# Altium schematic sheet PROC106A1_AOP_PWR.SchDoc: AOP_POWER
size 431 x 279 mm; Date: Not shown in title block; ApprovedBy: Not shown in title block; CheckedBy: Not shown in title block; Author: Not shown in title block; CompanyName: Not shown in title block; DrawnBy: Antony/Anand Ram; Engineer: Not shown in title block; Organization: Not shown in title block; Address1: Not shown in title block; Address2: Not shown in title block; Address3: Not shown in title block; Address4: Not shown in title block; DocumentNumber: 4; Revision: Use project parameter SCH_Rev; SheetNumber: 4; SheetTotal: 12; PageSetup: Record=PageOptions¦CenterHorizontal=True¦CenterVertical=True¦PrintScale=1.00¦XCorrection=1.00¦YCorrection=1.00¦PrintKind=0¦BorderSize=5000000¦LeftOffset=0¦BottomOffset=0¦Orientation=2¦PaperLength=1000¦PaperWidth=1000¦Scale=100¦PaperSource=15¦PrintQuality=600¦MediaType=1¦DitherType=10¦PaperKind=Letter¦PrintScaleMode=1
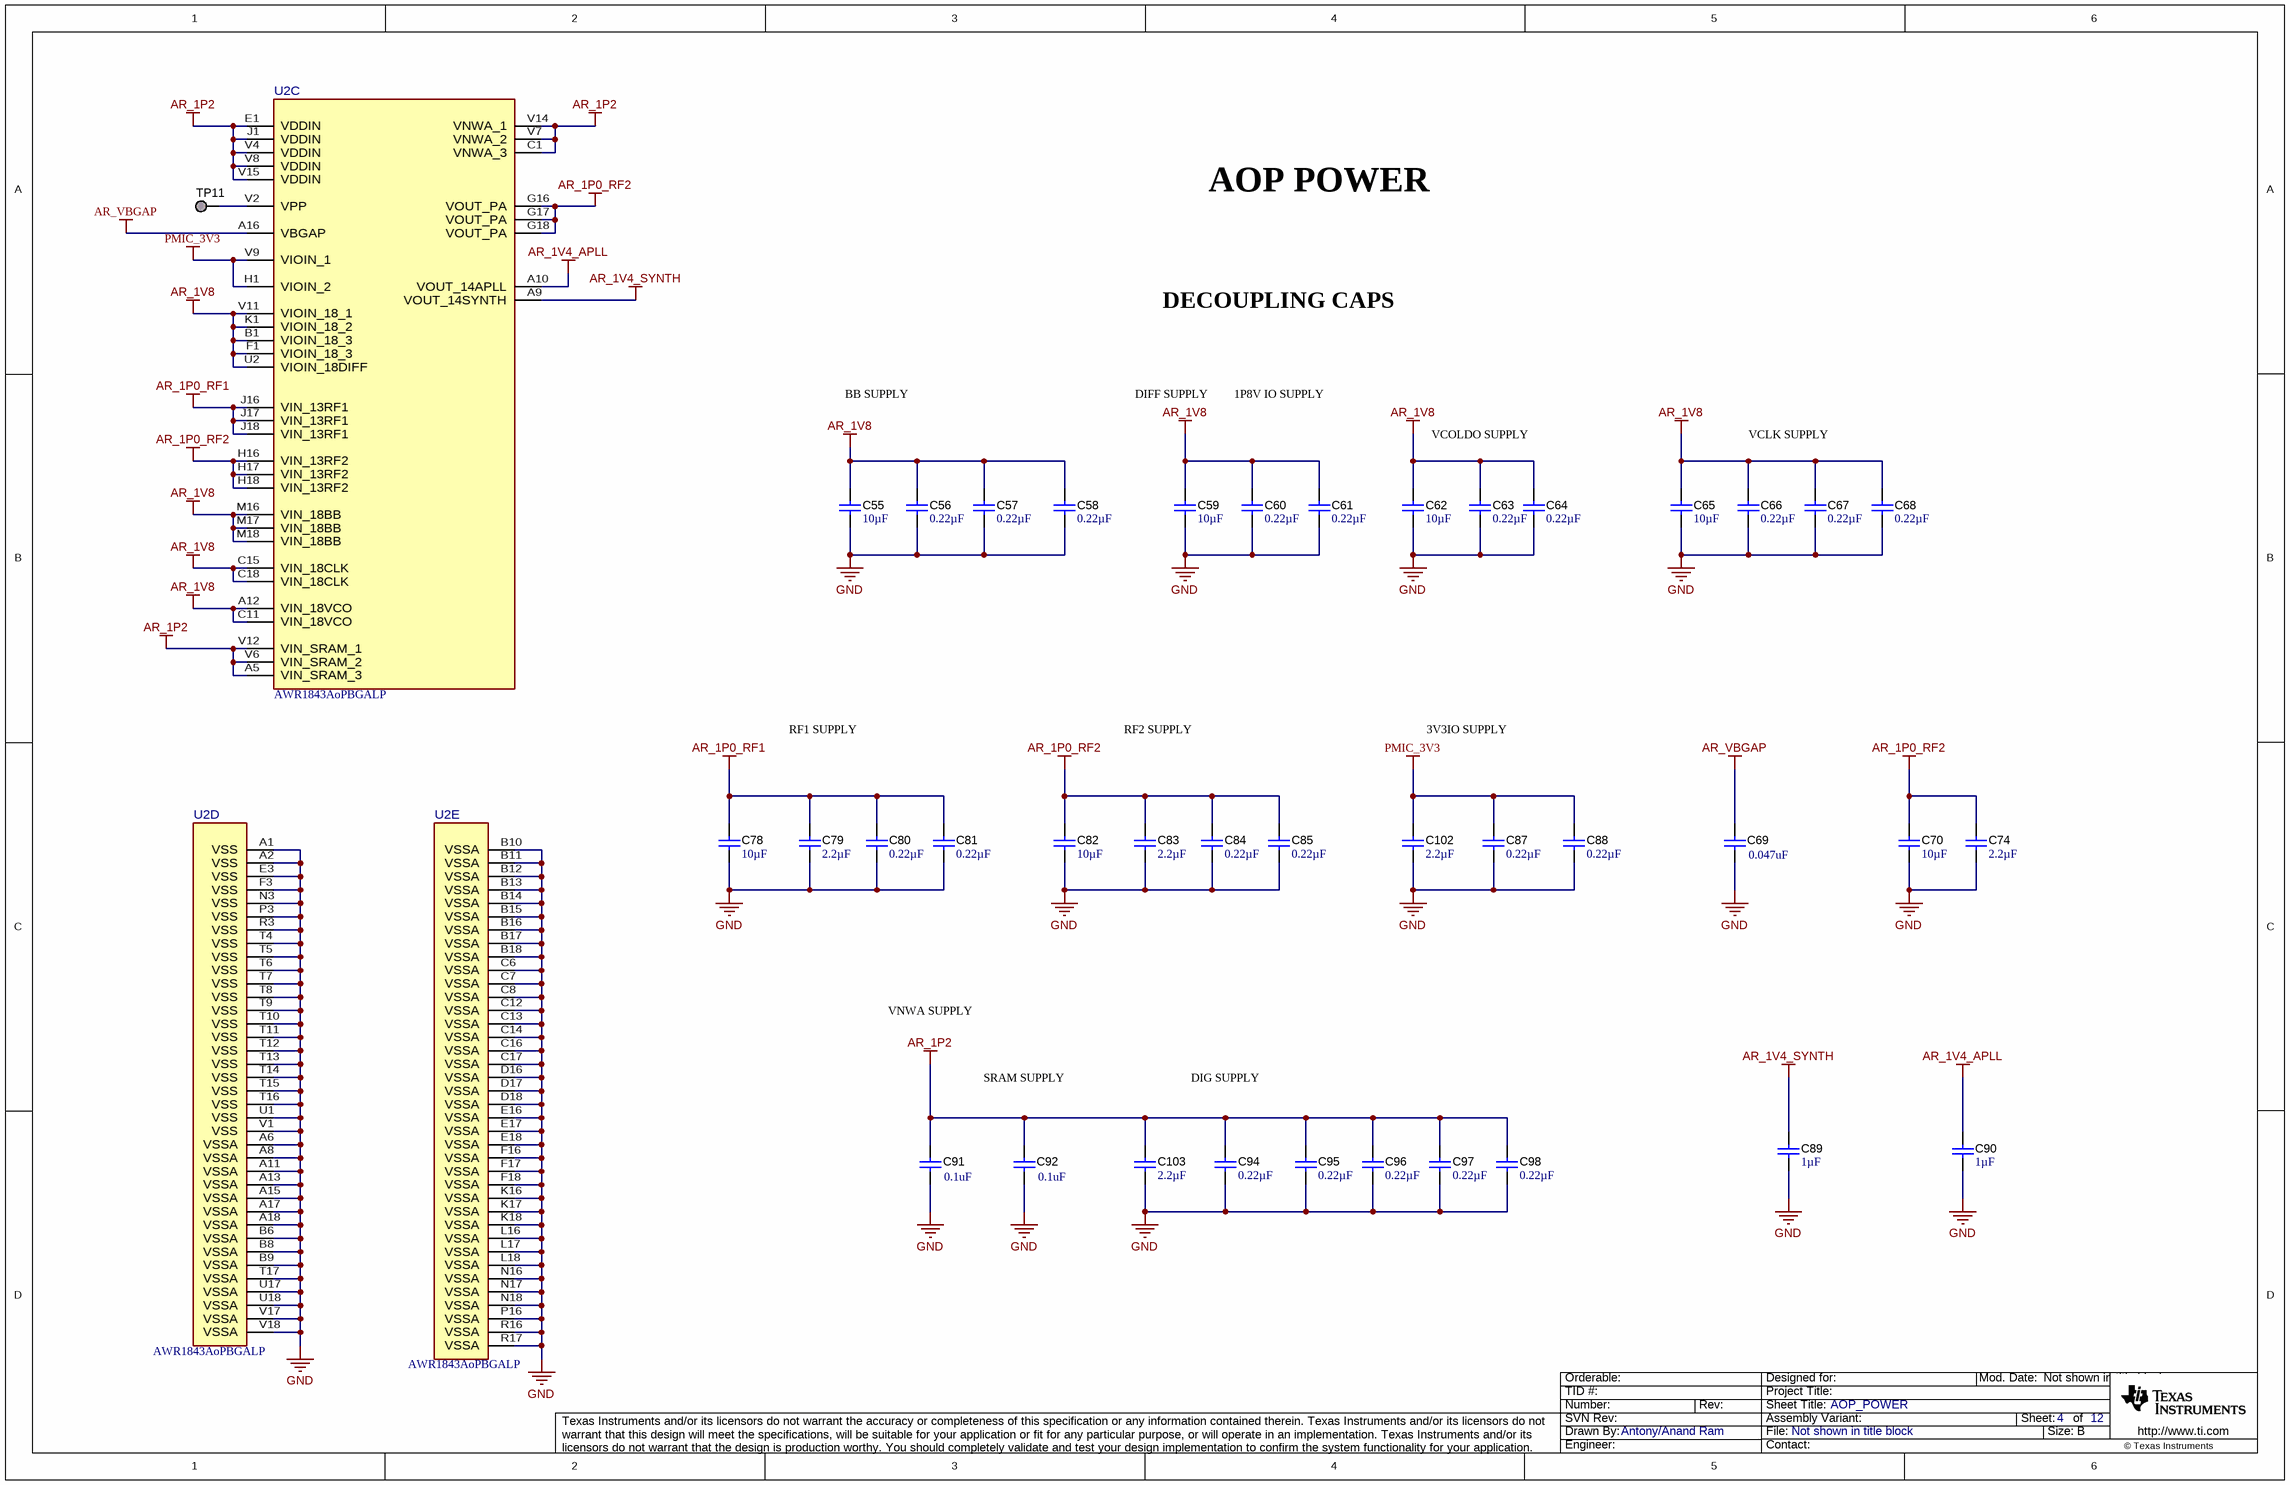
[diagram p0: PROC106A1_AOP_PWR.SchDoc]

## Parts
C55  Cap_F: 10µF  [0805L]  (hidden comment: GCM21BR71A106KE22L)
C56  ValueDisplayed: 0.22µF  [0402L]  (hidden comment: GCM155R71C224KE02D)
C57  ValueDisplayed: 0.22µF  [0402L]  (hidden comment: GCM155R71C224KE02D)
C58  ValueDisplayed: 0.22µF  [0402L]  (hidden comment: GCM155R71C224KE02D)
C59  Cap_F: 10µF  [0805L]  (hidden comment: GCM21BR71A106KE22L)
C60  ValueDisplayed: 0.22µF  [0402L]  (hidden comment: GCM155R71C224KE02D)
C61  ValueDisplayed: 0.22µF  [0402L]  (hidden comment: GCM155R71C224KE02D)
C62  Cap_F: 10µF  [0805L]  (hidden comment: GCM21BR71A106KE22L)
C63  ValueDisplayed: 0.22µF  [0402L]  (hidden comment: GCM155R71C224KE02D)
C64  ValueDisplayed: 0.22µF  [0402L]  (hidden comment: GCM155R71C224KE02D)
C65  Cap_F: 10µF  [0805L]  (hidden comment: GCM21BR71A106KE22L)
C66  ValueDisplayed: 0.22µF  [0402L]  (hidden comment: GCM155R71C224KE02D)
C67  ValueDisplayed: 0.22µF  [0402L]  (hidden comment: GCM155R71C224KE02D)
C68  ValueDisplayed: 0.22µF  [0402L]  (hidden comment: GCM155R71C224KE02D)
C69  ValueDisplayed: 0.047uF  [0402L]  (hidden comment: CGA2B3X7R1H473K050BB)
C70  Cap_F: 10µF  [0805L]  (hidden comment: GCM21BR71A106KE22L)
C74  Cap_F: 2.2µF  [0603L]  (hidden comment: GCM188R70J225KE22D)
C78  Cap_F: 10µF  [0805L]  (hidden comment: GCM21BR71A106KE22L)
C79  Cap_F: 2.2µF  [0603L]  (hidden comment: GCM188R70J225KE22D)
C80  ValueDisplayed: 0.22µF  [0402L]  (hidden comment: GCM155R71C224KE02D)
C81  ValueDisplayed: 0.22µF  [0402L]  (hidden comment: GCM155R71C224KE02D)
C82  Cap_F: 10µF  [0805L]  (hidden comment: GCM21BR71A106KE22L)
C83  Cap_F: 2.2µF  [0603L]  (hidden comment: GCM188R70J225KE22D)
C84  ValueDisplayed: 0.22µF  [0402L]  (hidden comment: GCM155R71C224KE02D)
C85  ValueDisplayed: 0.22µF  [0402L]  (hidden comment: GCM155R71C224KE02D)
C87  ValueDisplayed: 0.22µF  [0402L]  (hidden comment: GCM155R71C224KE02D)
C88  ValueDisplayed: 0.22µF  [0402L]  (hidden comment: GCM155R71C224KE02D)
C89  Cap_F: 1µF  [0603L]  (hidden comment: GCM188R71C105KA64D)
C90  Cap_F: 1µF  [0603L]  (hidden comment: GCM188R71C105KA64D)
C91  ValueDisplayed: 0.1uF  [0402L]  (hidden comment: GCM155R71C104KA55D)
C92  ValueDisplayed: 0.1uF  [0402L]  (hidden comment: GCM155R71C104KA55D)
C94  ValueDisplayed: 0.22µF  [0402L]  (hidden comment: GCM155R71C224KE02D)
C95  ValueDisplayed: 0.22µF  [0402L]  (hidden comment: GCM155R71C224KE02D)
C96  ValueDisplayed: 0.22µF  [0402L]  (hidden comment: GCM155R71C224KE02D)
C97  ValueDisplayed: 0.22µF  [0402L]  (hidden comment: GCM155R71C224KE02D)
C98  ValueDisplayed: 0.22µF  [0402L]  (hidden comment: GCM155R71C224KE02D)
C102  Cap_F: 2.2µF  [0603L]  (hidden comment: GCM188R70J225KE22D)
C103  Cap_F: 2.2µF  [0603L]  (hidden comment: GCM188R70J225KE22D)
TP11  TP_SM_1MM  [TP_SM_1MM]  (value not drawn)  (no BOM)
U2  AWR1843AoPBGALP  [ALP0180A-MFG]  (parts C,D,E of 5)

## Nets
AR_1P0_RF1: C78.1 C79.1 C80.1 C81.1 U2.J16(VIN_13RF1) U2.J17(VIN_13RF1) U2.J18(VIN_13RF1)
AR_1P0_RF2: C70.1 C74.1 C82.1 C83.1 C84.1 C85.1 U2.G16(VOUT_PA) U2.G17(VOUT_PA) U2.G18(VOUT_PA) U2.H16(VIN_13RF2) U2.H17(VIN_13RF2) U2.H18(VIN_13RF2)
AR_1P2: C91.2 C92.2 C94.1 C95.1 C96.1 C97.1 C98.1 C103.1 U2.A5(VIN_SRAM_3) U2.C1(VNWA_3) U2.E1(VDDIN) U2.J1(VDDIN) U2.V4(VDDIN) U2.V6(VIN_SRAM_2) U2.V7(VNWA_2) U2.V8(VDDIN) U2.V12(VIN_SRAM_1) U2.V14(VNWA_1) U2.V15(VDDIN)
AR_1V4_APLL: C90.1 U2.A10(VOUT_14APLL)
AR_1V4_SYNTH: C89.1 U2.A9(VOUT_14SYNTH)
AR_1V8: C55.1 C56.1 C57.1 C58.1 C59.1 C60.1 C61.1 C62.1 C63.1 C64.1 C65.1 C66.1 C67.1 C68.1 U2.A12(VIN_18VCO) U2.B1(VIOIN_18_3) U2.C11(VIN_18VCO) U2.C15(VIN_18CLK) U2.C18(VIN_18CLK) U2.F1(VIOIN_18_3) U2.K1(VIOIN_18_2) U2.M16(VIN_18BB) U2.M17(VIN_18BB) U2.M18(VIN_18BB) U2.U2(VIOIN_18DIFF) U2.V11(VIOIN_18_1)
AR_VBGAP: C69.1 U2.A16(VBGAP)
GND: C55.2 C56.2 C57.2 C58.2 C59.2 C60.2 C61.2 C62.2 C63.2 C64.2 C65.2 C66.2 C67.2 C68.2 C69.2 C70.2 C74.2 C78.2 C79.2 C80.2 C81.2 C82.2 C83.2 C84.2 C85.2 C87.2 C88.2 C89.2 C90.2 C91.1 C92.1 C94.2 C95.2 C96.2 C97.2 C98.2 C102.2 C103.2 U2.A1(VSS) U2.A2(VSS) U2.A6(VSSA) U2.A8(VSSA) U2.A11(VSSA) U2.A13(VSSA) U2.A15(VSSA) U2.A17(VSSA) U2.A18(VSSA) U2.B6(VSSA) U2.B8(VSSA) U2.B9(VSSA) U2.B10(VSSA) U2.B11(VSSA) U2.B12(VSSA) U2.B13(VSSA) U2.B14(VSSA) U2.B15(VSSA) U2.B16(VSSA) U2.B17(VSSA) U2.B18(VSSA) U2.C6(VSSA) U2.C7(VSSA) U2.C8(VSSA) U2.C12(VSSA) U2.C13(VSSA) U2.C14(VSSA) U2.C16(VSSA) U2.C17(VSSA) U2.D16(VSSA) U2.D17(VSSA) U2.D18(VSSA) U2.E3(VSS) U2.E16(VSSA) U2.E17(VSSA) U2.E18(VSSA) U2.F3(VSS) U2.F16(VSSA) U2.F17(VSSA) U2.F18(VSSA) U2.K16(VSSA) U2.K17(VSSA) U2.K18(VSSA) U2.L16(VSSA) U2.L17(VSSA) U2.L18(VSSA) U2.N3(VSS) U2.N16(VSSA) U2.N17(VSSA) U2.N18(VSSA) U2.P3(VSS) U2.P16(VSSA) U2.R3(VSS) U2.R16(VSSA) U2.R17(VSSA) U2.T4(VSS) U2.T5(VSS) U2.T6(VSS) U2.T7(VSS) U2.T8(VSS) U2.T9(VSS) U2.T10(VSS) U2.T11(VSS) U2.T12(VSS) U2.T13(VSS) U2.T14(VSS) U2.T15(VSS) U2.T16(VSS) U2.T17(VSSA) U2.U1(VSS) U2.U17(VSSA) U2.U18(VSSA) U2.V1(VSS) U2.V17(VSSA) U2.V18(VSSA)
PMIC_3V3: C87.1 C88.1 C102.1 U2.H1(VIOIN_2) U2.V9(VIOIN_1)
NetTP11_1: TP11.1 U2.V2(VPP)

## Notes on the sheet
- AOP POWER
- DECOUPLING CAPS
- BB SUPPLY
- DIFF SUPPLY
- 1P8V IO SUPPLY
- VCOLDO SUPPLY
- VCLK SUPPLY
- RF1 SUPPLY
- RF2 SUPPLY
- 3V3IO SUPPLY
- VNWA SUPPLY
- SRAM SUPPLY
- DIG SUPPLY

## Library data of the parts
C55 C59 C62 C65 C70 C78 C82 = CMP-0008017-2: CAP, CERM, 10 uF, 10 V, +/- 10%, X7R, 0805; Manufacturer: MuRata; Value: 10uF; AEC Category: Q200; Cap_Case: 0805; Polarized: N; SizeArea_mm2: 2.5; SizeAreaWB_mm2: 6.75; SizeX_mm: 2; SizeY_mm: 1.25; SizeZ_mm: 1.45; TaMax_C: 125°C; TaMin_C: -55°C; U/M: EA; Value1: Unknown; Value2: 10V
C56-C58 C60 C61 C63 C64 C66-C68 C80 C81 C84 C85 C87 C88 C94-C98 = CMP-0078265-1: CAP, CERM, 0.22 µF, 16 V,+/- 10%, X7R, AEC-Q200 Grade 1, 0402; Manufacturer: MuRata; Value: 0.22uF; AEC Category: Q200; AEC Grade: 1; AEC Qualified: Y; Cap_Case: 0402; Cap_F: 220nF; Polarized: N; SizeArea_mm2: 0.5; SizeAreaWB_mm2: 3; SizeZ_mm: 0.6; TaMax_C: 125°C; TaMin_C: -55°C; U/M: EA; Value2: 16V
C69 = CMP-0006330-2: CAP, CERM, 0.047 uF, 50 V, +/- 10%, X7R, AEC-Q200 Grade 1, 0402; Manufacturer: TDK; SizeZ_mm: 0.6; AEC Qualified: Y; Cap_F: 47nF; VDC_V: 50V; AEC Grade: 1; AEC Category: Q200; Cap_Case: 0402; ESR_ohm: 0.06407; IRMS_A: 6.46122dA; Polarized: N; SizeArea_mm2: 0.5; SizeAreaWB_mm2: 3; TaMax_C: 125°C; TaMin_C: -55°C; U/M: EA; Value1: 0.06407 ohm
C74 C79 C83 C102 C103 = CMP-0007134-5: CAP, CERM, 2.2 uF, 6.3 V, +/- 10%, X7R, AEC-Q200 Grade 1, 0603; Manufacturer: MuRata; Value: 2.2uF; AEC Category: Q200; AEC Grade: 1; AEC Qualified: Y; Cap_Case: 0603; Polarized: N; SizeArea_mm2: 1.28; SizeAreaWB_mm2: 4.68; SizeX_mm: 1.6; SizeY_mm: 0.8; TaMax_C: 125°C; TaMin_C: -55°C; U/M: EA; Value1: Unknown; Value2: 6.3V
C89 C90 = CMP-0007136-5: CAP, CERM, 1 uF, 16 V, +/- 10%, X7R, AEC-Q200 Grade 1, 0603; Manufacturer: MuRata; TaMin_C: -55°C; Polarized: N; SizeAreaWB_mm2: 4.68; U/M: EA; Value: 1uF; TaMax_C: 125°C; SizeZ_mm: 1; SizeX_mm: 1.6; SizeY_mm: 0.8; Cap_Case: 0603; Value2: 16V; SizeArea_mm2: 1.28; AEC Qualified: Y; AEC Category: Q200; Value1: Unknown
C91 C92 = CMP-0006351-2: CAP, CERM, 0.1 uF, 16 V, +/- 10%, X7R, 0402; Manufacturer: MuRata; Cap_F: 100nF; SizeZ_mm: 0.6; VDC_V: 16V; AEC Category: Q200; Cap_Case: 0402; Polarized: N; SizeArea_mm2: 0.5; SizeAreaWB_mm2: 3; SizeX_mm: 1; TaMax_C: 125°C; TaMin_C: -55°C; U/M: EA; Value1: Unknown; Value: 0.1uF
TP11 = CMP-0003825-1: 1mm Test Point, SMT; Manufacturer: Any
U2 = CMP-0090288-2: Manufacturer: Texas Instruments; Standoff Height: 0.31mm; SizeZ_mm: 0.965mm; AEC Category: Q200; CompType: IC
